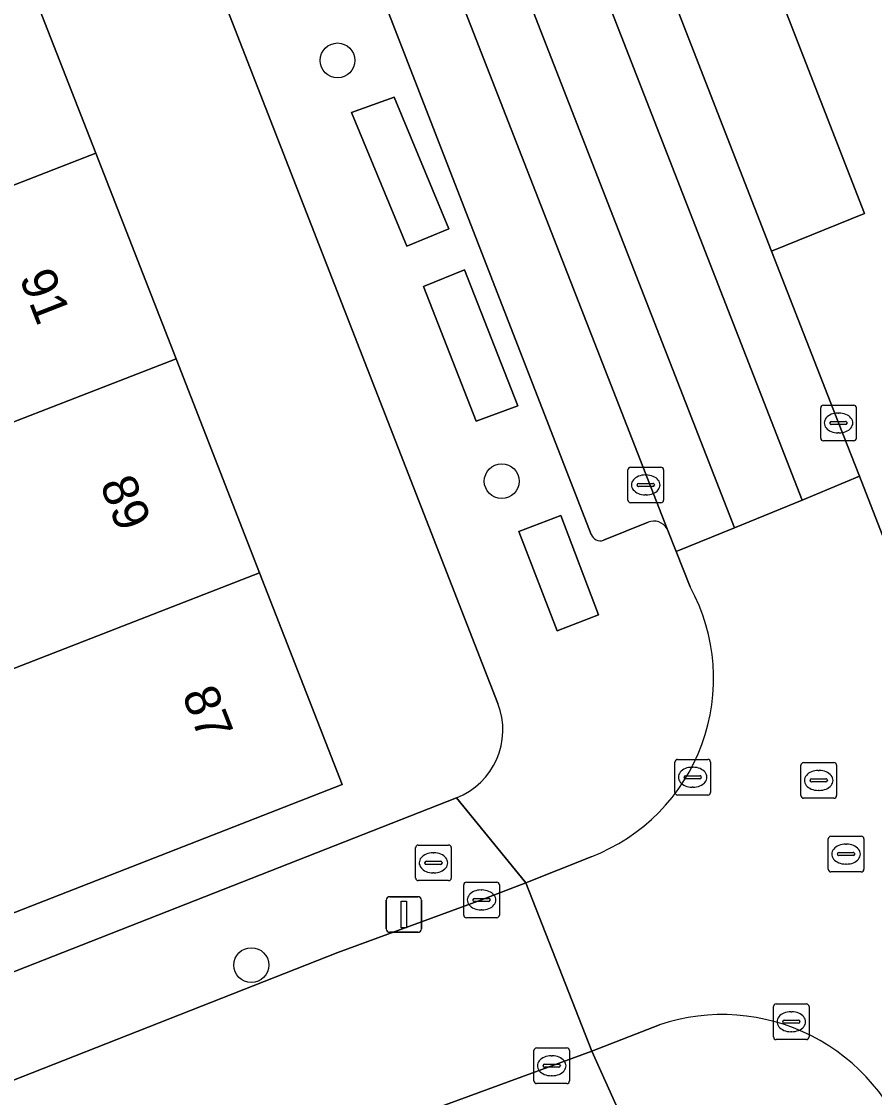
# Model space of a CAD drawing. Extents: x 159680 to 160786, y 387323 to 388340.
# Drawn here: x 160127.91 to 160151.87, y 387907.82 to 387938.03 of the extents above; entities that cross this region are included whole.
import ezdxf

# ---------------------------------------------------------------- set-up
doc = ezdxf.new("R2010")
doc.units = 0
for name, color, linetype in [('IMGEO_Boom', 7, 'Continuous'), ('IMGEO_Brandkraan', 7, 'Continuous'), ('IMGEO_Erf', 7, 'Continuous'), ('IMGEO_Groenvoorziening', 7, 'Continuous'), ('IMGEO_Kolk', 7, 'Continuous'), ('IMGEO_Lichtmast', 7, 'Continuous'), ('IMGEO_Pand', 7, 'Continuous'), ('IMGEO_Pand_nummerreeks', 7, 'Continuous'), ('IMGEO_Parkeervlak_open', 7, 'Continuous'), ('IMGEO_Rijbaan_lokaal_gesloten', 7, 'Continuous'), ('IMGEO_Rijbaan_lokaal_open', 7, 'Continuous'), ('IMGEO_Rioolput', 7, 'Continuous'), ('IMGEO_Voetpad_open', 7, 'Continuous')]:
    doc.layers.add(name, color=color, linetype=linetype)

msp = doc.modelspace()

# ---------------------------------------------------------------- linework, layer by layer
at = {"layer": 'IMGEO_Boom'}
for centre in [(160136.79, 387936.94), (160141.402, 387925.126), (160134.368, 387911.539)]:
    msp.add_circle(centre, 0.489, dxfattribs=at)
at = {"layer": 'IMGEO_Brandkraan'}
for p, q in [((160138.985, 387913.984), (160138.985, 387914.836)), ((160139.06, 387914.91), (160139.912, 387914.91)), ((160139.986, 387914.836), (160139.986, 387913.984)), ((160139.473, 387914.69), (160139.498, 387914.69)), ((160139.244, 387914.404), (160139.244, 387914.416)), ((160139.682, 387914.367), (160139.284, 387914.367)), ((160139.287, 387914.453), (160139.685, 387914.453)), ((160139.728, 387914.416), (160139.728, 387914.404)), ((160139.912, 387913.91), (160139.06, 387913.91)), ((160139.496, 387914.13), (160139.471, 387914.13))]:
    msp.add_line(p, q, dxfattribs=at)
for points in [[(160138.985, 387913.984), (160138.985, 387914.836)], [(160139.06, 387914.91), (160139.912, 387914.91)], [(160139.986, 387914.836), (160139.986, 387913.984)], [(160139.912, 387913.91), (160139.06, 387913.91)]]:
    msp.add_lwpolyline(points, dxfattribs=at)
for centre, radius, start, end in [((160139.062, 387914.834), 0.0765, 91.552, 178.448), ((160139.062, 387914.834), 0.0765, 91.552, 178.448), ((160139.91, 387914.834), 0.0765, 1.552, 88.448), ((160139.91, 387914.834), 0.0765, 1.552, 88.448), ((160139.284, 387914.413), 0.0403, 85.8775, 175.7526), ((160139.281, 387914.403), 0.0366, 178.938, 274.7102), ((160139.685, 387914.41), 0.043, 264.8664, 352.4533), ((160139.689, 387914.415), 0.0386, 1.7309, 96.639), ((160139.062, 387913.986), 0.0765, 181.552, 268.448), ((160139.062, 387913.986), 0.0765, 181.552, 268.448), ((160139.91, 387913.986), 0.0765, 271.552, 358.448), ((160139.91, 387913.986), 0.0765, 271.552, 358.448)]:
    msp.add_arc(centre, radius, start, end, dxfattribs=at)
for centre, major_axis, ratio, start_param, end_param in [((160139.472, 387914.41), (-0.387, 0.002), 0.722429, 4.712389, 7.853982), ((160139.497, 387914.41), (-0.39, 0.002), 0.717154, 1.570796, 4.712389)]:
    msp.add_ellipse(centre, major_axis=major_axis, ratio=ratio, start_param=start_param, end_param=end_param, dxfattribs=at)
at = {"layer": 'IMGEO_Erf'}
for points in [[(160117.173, 387970.931), (160116.204, 387970.698), (160110.655, 387969.121), (160096.541, 387964.792), (160097.787, 387961.694), (160101.244, 387963.071), (160103.173, 387958.229), (160099.716, 387956.852), (160101.306, 387952.888), (160103.114, 387948.275), (160105.857, 387949.308), (160107.114, 387945.971), (160108.578, 387942.084), (160105.834, 387941.051), (160115.683, 387915.296), (160115.897, 387915.38), (160116.002, 387915.162), (160118.459, 387916.115), (160119.792, 387912.679), (160117.335, 387911.726), (160118.086, 387909.722), (160118.757, 387907.847), (160120.676, 387908.594), (160140.13, 387916.234)], [(160141.297, 387918.886), (160132.396, 387941.704)]]:
    msp.add_lwpolyline(points, dxfattribs=at)
msp.add_lwpolyline([(160117.557, 387942.943), (160115.165, 387949.099), (160112.885, 387954.968), (160110.623, 387960.789), (160118.478, 387963.856), (160120.754, 387958.026), (160123.043, 387952.16), (160125.445, 387946.008), (160127.727, 387940.161), (160130.001, 387934.334), (160132.253, 387928.565), (160134.6, 387922.552), (160136.92, 387916.607), (160128.993, 387913.512), (160125.678, 387912.224), (160123.361, 387918.186), (160126.676, 387919.474), (160124.339, 387925.49), (160122.096, 387931.263), (160119.83, 387937.093)], close=True, dxfattribs=at)
msp.add_arc((160139.382, 387918.146), 2.053, 291.3752, 21.1214, dxfattribs=at)
at = {"layer": 'IMGEO_Groenvoorziening'}
msp.add_lwpolyline([(160146.101, 387981.164), (160142.324, 387979.675), (160138.864, 387978.366), (160131.76, 387975.659), (160133.244, 387971.861), (160134.554, 387968.586), (160135.868, 387965.217), (160137.991, 387959.814), (160140.621, 387960.823), (160151.591, 387932.646), (160148.978, 387931.586), (160150.863, 387926.76), (160151.456, 387925.265), (160152.156, 387923.465), (160154.538, 387924.338), (160161.401, 387927.165), (160164.49, 387928.393)], dxfattribs=at)
for points in [[(160138.74, 387931.727), (160139.916, 387932.215), (160138.385, 387935.91), (160137.185, 387935.478)], [(160140.685, 387926.81), (160141.852, 387927.243), (160140.359, 387931.058), (160139.202, 387930.595)], [(160142.963, 387920.925), (160144.125, 387921.377), (160143.065, 387924.166), (160141.879, 387923.716)]]:
    msp.add_lwpolyline(points, close=True, dxfattribs=at)
at = {"layer": 'IMGEO_Kolk'}
for p, q in [((160150.362, 387926.334), (160150.362, 387927.186)), ((160150.437, 387927.26), (160151.289, 387927.26)), ((160151.363, 387927.186), (160151.363, 387926.334)), ((160150.85, 387927.04), (160150.875, 387927.04)), ((160150.621, 387926.754), (160150.621, 387926.766)), ((160151.059, 387926.717), (160150.661, 387926.717)), ((160150.664, 387926.803), (160151.062, 387926.803)), ((160151.105, 387926.766), (160151.105, 387926.754)), ((160151.289, 387926.26), (160150.437, 387926.26)), ((160150.873, 387926.48), (160150.848, 387926.48)), ((160144.948, 387924.594), (160144.948, 387925.446)), ((160145.023, 387925.52), (160145.875, 387925.52)), ((160145.949, 387925.446), (160145.949, 387924.594)), ((160145.25, 387925.063), (160145.648, 387925.063)), ((160145.436, 387925.3), (160145.461, 387925.3)), ((160145.207, 387925.014), (160145.207, 387925.026)), ((160145.645, 387924.977), (160145.247, 387924.977)), ((160145.691, 387925.026), (160145.691, 387925.014)), ((160145.875, 387924.52), (160145.023, 387924.52)), ((160145.459, 387924.74), (160145.434, 387924.74)), ((160146.266, 387916.388), (160146.266, 387917.24)), ((160146.341, 387917.314), (160147.193, 387917.314)), ((160147.267, 387917.24), (160147.267, 387916.388)), ((160146.754, 387917.094), (160146.779, 387917.094)), ((160146.525, 387916.808), (160146.525, 387916.82)), ((160146.963, 387916.771), (160146.565, 387916.771)), ((160146.568, 387916.857), (160146.966, 387916.857)), ((160147.009, 387916.82), (160147.009, 387916.808)), ((160147.193, 387916.314), (160146.341, 387916.314)), ((160146.777, 387916.534), (160146.752, 387916.534)), ((160140.41, 387913.868), (160141.262, 387913.868)), ((160140.335, 387912.942), (160140.335, 387913.794)), ((160140.823, 387913.648), (160140.848, 387913.648)), ((160141.336, 387913.794), (160141.336, 387912.942)), ((160140.594, 387913.362), (160140.594, 387913.374)), ((160141.032, 387913.325), (160140.634, 387913.325)), ((160140.637, 387913.411), (160141.035, 387913.411)), ((160141.078, 387913.374), (160141.078, 387913.362)), ((160140.846, 387913.088), (160140.821, 387913.088)), ((160141.262, 387912.868), (160140.41, 387912.868)), ((160149.036, 387909.522), (160149.036, 387910.374)), ((160149.111, 387910.448), (160149.963, 387910.448)), ((160150.037, 387910.374), (160150.037, 387909.522)), ((160149.295, 387909.942), (160149.295, 387909.954)), ((160149.338, 387909.991), (160149.736, 387909.991)), ((160149.524, 387910.228), (160149.549, 387910.228)), ((160149.779, 387909.954), (160149.779, 387909.942)), ((160149.733, 387909.905), (160149.335, 387909.905)), ((160149.547, 387909.668), (160149.522, 387909.668)), ((160149.963, 387909.448), (160149.111, 387909.448)), ((160142.306, 387908.286), (160142.306, 387909.138)), ((160142.381, 387909.212), (160143.233, 387909.212)), ((160143.307, 387909.138), (160143.307, 387908.286)), ((160142.608, 387908.755), (160143.006, 387908.755)), ((160142.794, 387908.992), (160142.819, 387908.992)), ((160142.565, 387908.706), (160142.565, 387908.718)), ((160143.003, 387908.669), (160142.605, 387908.669)), ((160142.817, 387908.432), (160142.792, 387908.432)), ((160143.049, 387908.718), (160143.049, 387908.706)), ((160143.233, 387908.212), (160142.381, 387908.212))]:
    msp.add_line(p, q, dxfattribs=at)
for points in [[(160150.362, 387926.334), (160150.362, 387927.186)], [(160150.437, 387927.26), (160151.289, 387927.26)], [(160151.363, 387927.186), (160151.363, 387926.334)], [(160151.289, 387926.26), (160150.437, 387926.26)], [(160144.948, 387924.594), (160144.948, 387925.446)], [(160145.023, 387925.52), (160145.875, 387925.52)], [(160145.949, 387925.446), (160145.949, 387924.594)], [(160145.875, 387924.52), (160145.023, 387924.52)], [(160146.266, 387916.388), (160146.266, 387917.24)], [(160146.341, 387917.314), (160147.193, 387917.314)], [(160147.267, 387917.24), (160147.267, 387916.388)], [(160147.193, 387916.314), (160146.341, 387916.314)], [(160140.41, 387913.868), (160141.262, 387913.868)], [(160140.335, 387912.942), (160140.335, 387913.794)], [(160141.336, 387913.794), (160141.336, 387912.942)], [(160141.262, 387912.868), (160140.41, 387912.868)], [(160149.036, 387909.522), (160149.036, 387910.374)], [(160149.111, 387910.448), (160149.963, 387910.448)], [(160150.037, 387910.374), (160150.037, 387909.522)], [(160149.963, 387909.448), (160149.111, 387909.448)], [(160142.306, 387908.286), (160142.306, 387909.138)], [(160142.381, 387909.212), (160143.233, 387909.212)], [(160143.307, 387909.138), (160143.307, 387908.286)], [(160143.233, 387908.212), (160142.381, 387908.212)]]:
    msp.add_lwpolyline(points, dxfattribs=at)
for centre, radius, start, end in [((160150.439, 387927.184), 0.0765, 91.552, 178.448), ((160150.439, 387927.184), 0.0765, 91.552, 178.448), ((160151.287, 387927.184), 0.0765, 1.552, 88.448), ((160151.287, 387927.184), 0.0765, 1.552, 88.448), ((160150.661, 387926.763), 0.0403, 85.8775, 175.7526), ((160150.658, 387926.753), 0.0366, 178.938, 274.7102), ((160151.062, 387926.76), 0.043, 264.8664, 352.4533), ((160151.066, 387926.765), 0.0386, 1.7309, 96.639), ((160150.439, 387926.336), 0.0765, 181.552, 268.448), ((160150.439, 387926.336), 0.0765, 181.552, 268.448), ((160151.287, 387926.336), 0.0765, 271.552, 358.448), ((160151.287, 387926.336), 0.0765, 271.552, 358.448), ((160145.025, 387925.444), 0.0765, 91.552, 178.448), ((160145.025, 387925.444), 0.0765, 91.552, 178.448), ((160145.873, 387925.444), 0.0765, 1.552, 88.448), ((160145.873, 387925.444), 0.0765, 1.552, 88.448), ((160145.247, 387925.023), 0.0403, 85.8775, 175.7526), ((160145.652, 387925.025), 0.0386, 1.7309, 96.639), ((160145.244, 387925.013), 0.0366, 178.938, 274.7102), ((160145.648, 387925.02), 0.043, 264.8664, 352.4533), ((160145.025, 387924.596), 0.0765, 181.552, 268.448), ((160145.025, 387924.596), 0.0765, 181.552, 268.448), ((160145.873, 387924.596), 0.0765, 271.552, 358.448), ((160145.873, 387924.596), 0.0765, 271.552, 358.448), ((160146.343, 387917.238), 0.0765, 91.552, 178.448), ((160146.343, 387917.238), 0.0765, 91.552, 178.448), ((160147.191, 387917.238), 0.0765, 1.552, 88.448), ((160147.191, 387917.238), 0.0765, 1.552, 88.448), ((160146.565, 387916.817), 0.0403, 85.8775, 175.7526), ((160146.562, 387916.807), 0.0366, 178.938, 274.7102), ((160146.966, 387916.814), 0.043, 264.8664, 352.4533), ((160146.97, 387916.819), 0.0386, 1.7309, 96.639), ((160146.343, 387916.39), 0.0765, 181.552, 268.448), ((160146.343, 387916.39), 0.0765, 181.552, 268.448), ((160147.191, 387916.39), 0.0765, 271.552, 358.448), ((160147.191, 387916.39), 0.0765, 271.552, 358.448), ((160140.412, 387913.792), 0.0765, 91.552, 178.448), ((160140.412, 387913.792), 0.0765, 91.552, 178.448), ((160141.26, 387913.792), 0.0765, 1.552, 88.448), ((160141.26, 387913.792), 0.0765, 1.552, 88.448), ((160140.634, 387913.371), 0.0403, 85.8775, 175.7526), ((160140.631, 387913.361), 0.0366, 178.938, 274.7102), ((160141.035, 387913.368), 0.043, 264.8664, 352.4533), ((160141.039, 387913.373), 0.0386, 1.7309, 96.639), ((160140.412, 387912.944), 0.0765, 181.552, 268.448), ((160140.412, 387912.944), 0.0765, 181.552, 268.448), ((160141.26, 387912.944), 0.0765, 271.552, 358.448), ((160141.26, 387912.944), 0.0765, 271.552, 358.448), ((160149.113, 387910.372), 0.0765, 91.552, 178.448), ((160149.113, 387910.372), 0.0765, 91.552, 178.448), ((160149.961, 387910.372), 0.0765, 1.552, 88.448), ((160149.961, 387910.372), 0.0765, 1.552, 88.448), ((160149.335, 387909.951), 0.0403, 85.8775, 175.7526), ((160149.332, 387909.941), 0.0366, 178.938, 274.7102), ((160149.736, 387909.948), 0.043, 264.8664, 352.4533), ((160149.74, 387909.953), 0.0386, 1.7309, 96.639), ((160149.113, 387909.524), 0.0765, 181.552, 268.448), ((160149.113, 387909.524), 0.0765, 181.552, 268.448), ((160149.961, 387909.524), 0.0765, 271.552, 358.448), ((160149.961, 387909.524), 0.0765, 271.552, 358.448), ((160142.383, 387909.136), 0.0765, 91.552, 178.448), ((160142.383, 387909.136), 0.0765, 91.552, 178.448), ((160143.231, 387909.136), 0.0765, 1.552, 88.448), ((160143.231, 387909.136), 0.0765, 1.552, 88.448), ((160142.605, 387908.715), 0.0403, 85.8775, 175.7526), ((160143.01, 387908.717), 0.0386, 1.7309, 96.639), ((160142.602, 387908.705), 0.0366, 178.938, 274.7102), ((160143.006, 387908.712), 0.043, 264.8664, 352.4533), ((160142.383, 387908.288), 0.0765, 181.552, 268.448), ((160142.383, 387908.288), 0.0765, 181.552, 268.448), ((160143.231, 387908.288), 0.0765, 271.552, 358.448), ((160143.231, 387908.288), 0.0765, 271.552, 358.448)]:
    msp.add_arc(centre, radius, start, end, dxfattribs=at)
for centre, major_axis, ratio, start_param, end_param in [((160150.849, 387926.76), (-0.387, 0.002), 0.722429, 4.712389, 7.853982), ((160150.874, 387926.76), (-0.39, 0.002), 0.717154, 1.570796, 4.712389), ((160145.435, 387925.02), (-0.387, 0.002), 0.722429, 4.712389, 7.853982), ((160145.46, 387925.02), (-0.39, 0.002), 0.717154, 1.570796, 4.712389), ((160146.753, 387916.814), (-0.387, 0.002), 0.722429, 4.712389, 7.853982), ((160146.778, 387916.814), (-0.39, 0.002), 0.717154, 1.570796, 4.712389), ((160140.822, 387913.368), (-0.387, 0.002), 0.722429, 4.712389, 7.853982), ((160140.847, 387913.368), (-0.39, 0.002), 0.717154, 1.570796, 4.712389), ((160149.523, 387909.948), (-0.387, 0.002), 0.722429, 4.712389, 7.853982), ((160149.548, 387909.948), (-0.39, 0.002), 0.717154, 1.570796, 4.712389), ((160142.793, 387908.712), (-0.387, 0.002), 0.722429, 4.712389, 7.853982), ((160142.818, 387908.712), (-0.39, 0.002), 0.717154, 1.570796, 4.712389)]:
    msp.add_ellipse(centre, major_axis=major_axis, ratio=ratio, start_param=start_param, end_param=end_param, dxfattribs=at)
at = {"layer": 'IMGEO_Lichtmast'}
for p, q in [((160138.157, 387912.56), (160138.157, 387913.36)), ((160138.157, 387913.36), (160138.157, 387912.56)), ((160138.257, 387913.46), (160139.047, 387913.46)), ((160139.047, 387913.46), (160138.257, 387913.46)), ((160139.147, 387913.36), (160139.147, 387912.56)), ((160139.147, 387912.56), (160139.147, 387913.36)), ((160139.047, 387912.46), (160138.257, 387912.46)), ((160138.257, 387912.46), (160139.047, 387912.46))]:
    msp.add_line(p, q, dxfattribs=at)
msp.add_lwpolyline([(160138.577, 387913.335), (160138.727, 387913.335), (160138.727, 387912.585), (160138.577, 387912.585), (160138.577, 387913.335)], dxfattribs=at)
for centre, start, end in [((160138.257, 387913.36), 90, 180), ((160138.257, 387913.36), 90, 180), ((160139.047, 387913.36), 0, 90), ((160139.047, 387913.36), 360, 90), ((160138.257, 387912.56), 180, 270), ((160138.257, 387912.56), 180, 270), ((160139.047, 387912.56), 270, 0), ((160139.047, 387912.56), 270, 0)]:
    msp.add_arc(centre, 0.1, start, end, dxfattribs=at)
at = {"layer": 'IMGEO_Pand'}
for points in [[(160130.001, 387934.334), (160127.727, 387940.161), (160119.83, 387937.093), (160122.096, 387931.263)], [(160122.096, 387931.263), (160124.339, 387925.49), (160132.253, 387928.565), (160130.001, 387934.334)], [(160134.6, 387922.552), (160132.253, 387928.565), (160124.339, 387925.49), (160126.676, 387919.474)], [(160134.6, 387922.552), (160126.676, 387919.474), (160123.361, 387918.186), (160125.678, 387912.224), (160128.993, 387913.512), (160136.92, 387916.607)]]:
    msp.add_lwpolyline(points, close=True, dxfattribs=at)
at = {"layer": 'IMGEO_Parkeervlak_open'}
for points in [[(160146.047, 387923.792), (160130.492, 387963.653)], [(160128.848, 387962.268), (160129.136, 387961.665), (160143.916, 387923.629)], [(160144.26, 387923.466), (160145.519, 387923.974)]]:
    msp.add_lwpolyline(points, dxfattribs=at)
msp.add_lwpolyline([(160137.991, 387959.814), (160143.514, 387945.629), (160148.978, 387931.586), (160151.591, 387932.646), (160140.621, 387960.823)], close=True, dxfattribs=at)
for centre, radius, start, end in [((160145.678, 387923.579), 0.426, 30.0107, 111.9515), ((160144.177, 387923.736), 0.282, 202.1965, 287.0968)]:
    msp.add_arc(centre, radius, start, end, dxfattribs=at)
at = {"layer": 'IMGEO_Rijbaan_lokaal_gesloten'}
for points in [[(160137.991, 387959.814), (160135.868, 387965.217), (160134.554, 387968.586), (160132.955, 387967.915), (160149.838, 387924.597), (160151.456, 387925.265), (160150.863, 387926.76), (160148.978, 387931.586), (160143.514, 387945.629)], [(160131.042, 387967.15), (160129.403, 387966.471), (160130.344, 387964.037), (160130.492, 387963.653), (160146.047, 387923.792), (160146.305, 387923.152), (160147.944, 387923.815)]]:
    msp.add_lwpolyline(points, close=True, dxfattribs=at)
at = {"layer": 'IMGEO_Rijbaan_lokaal_open'}
msp.add_lwpolyline([(160132.955, 387967.915), (160131.042, 387967.15), (160147.944, 387923.815), (160149.838, 387924.597)], close=True, dxfattribs=at)
for points in [[(160153.052, 387921.218), (160152.156, 387923.465), (160151.456, 387925.265), (160149.838, 387924.597), (160147.944, 387923.815), (160146.305, 387923.152), (160146.7, 387922.155)], [(160143.916, 387914.582), (160142.084, 387913.853), (160143.935, 387909.124), (160145.839, 387909.866)], [(160138.953, 387907.297), (160142.807, 387908.712), (160143.935, 387909.124), (160142.084, 387913.853), (160140.836, 387913.368), (160136.795, 387911.888), (160118.168, 387904.562)]]:
    msp.add_lwpolyline(points, dxfattribs=at)
for centre, radius, start, end in [((160141.997, 387919.586), 5.359, 290.9811, 28.6498), ((160147.594, 387904.599), 5.552, 17.7433, 108.4323)]:
    msp.add_arc(centre, radius, start, end, dxfattribs=at)
at = {"layer": 'IMGEO_Rioolput'}
for p, q in [((160149.882, 387917.224), (160150.734, 387917.224)), ((160149.807, 387916.298), (160149.807, 387917.15)), ((160150.295, 387917.004), (160150.32, 387917.004)), ((160150.808, 387917.15), (160150.808, 387916.298)), ((160150.066, 387916.718), (160150.066, 387916.73)), ((160150.504, 387916.681), (160150.106, 387916.681)), ((160150.109, 387916.767), (160150.507, 387916.767)), ((160150.55, 387916.73), (160150.55, 387916.718)), ((160150.318, 387916.444), (160150.293, 387916.444)), ((160150.734, 387916.224), (160149.882, 387916.224)), ((160150.575, 387914.229), (160150.575, 387915.081)), ((160150.65, 387915.155), (160151.502, 387915.155)), ((160151.576, 387915.081), (160151.576, 387914.229)), ((160151.063, 387914.935), (160151.088, 387914.935)), ((160150.834, 387914.649), (160150.834, 387914.661)), ((160151.272, 387914.612), (160150.874, 387914.612)), ((160150.877, 387914.698), (160151.275, 387914.698)), ((160151.318, 387914.661), (160151.318, 387914.649)), ((160151.086, 387914.375), (160151.061, 387914.375)), ((160151.502, 387914.155), (160150.65, 387914.155))]:
    msp.add_line(p, q, dxfattribs=at)
for points in [[(160149.882, 387917.224), (160150.734, 387917.224)], [(160149.807, 387916.298), (160149.807, 387917.15)], [(160150.808, 387917.15), (160150.808, 387916.298)], [(160150.734, 387916.224), (160149.882, 387916.224)], [(160150.575, 387914.229), (160150.575, 387915.081)], [(160150.65, 387915.155), (160151.502, 387915.155)], [(160151.576, 387915.081), (160151.576, 387914.229)], [(160151.502, 387914.155), (160150.65, 387914.155)]]:
    msp.add_lwpolyline(points, dxfattribs=at)
for centre, radius, start, end in [((160149.884, 387917.148), 0.0765, 91.552, 178.448), ((160149.884, 387917.148), 0.0765, 91.552, 178.448), ((160150.732, 387917.148), 0.0765, 1.552, 88.448), ((160150.732, 387917.148), 0.0765, 1.552, 88.448), ((160150.106, 387916.727), 0.0403, 85.8775, 175.7526), ((160150.103, 387916.717), 0.0366, 178.938, 274.7102), ((160150.507, 387916.724), 0.043, 264.8664, 352.4533), ((160150.511, 387916.729), 0.0386, 1.7309, 96.639), ((160149.884, 387916.3), 0.0765, 181.552, 268.448), ((160149.884, 387916.3), 0.0765, 181.552, 268.448), ((160150.732, 387916.3), 0.0765, 271.552, 358.448), ((160150.732, 387916.3), 0.0765, 271.552, 358.448), ((160150.652, 387915.079), 0.0765, 91.552, 178.448), ((160150.652, 387915.079), 0.0765, 91.552, 178.448), ((160151.5, 387915.079), 0.0765, 1.552, 88.448), ((160151.5, 387915.079), 0.0765, 1.552, 88.448), ((160150.874, 387914.658), 0.0403, 85.8775, 175.7526), ((160150.871, 387914.648), 0.0366, 178.938, 274.7102), ((160151.275, 387914.655), 0.043, 264.8664, 352.4533), ((160151.279, 387914.66), 0.0386, 1.7309, 96.639), ((160150.652, 387914.231), 0.0765, 181.552, 268.448), ((160150.652, 387914.231), 0.0765, 181.552, 268.448), ((160151.5, 387914.231), 0.0765, 271.552, 358.448), ((160151.5, 387914.231), 0.0765, 271.552, 358.448)]:
    msp.add_arc(centre, radius, start, end, dxfattribs=at)
for centre, major_axis, ratio, start_param, end_param in [((160150.294, 387916.724), (-0.387, 0.002), 0.722429, 4.712389, 7.853982), ((160150.319, 387916.724), (-0.39, 0.002), 0.717154, 1.570796, 4.712389), ((160151.062, 387914.655), (-0.387, 0.002), 0.722429, 4.712389, 7.853982), ((160151.087, 387914.655), (-0.39, 0.002), 0.717154, 1.570796, 4.712389)]:
    msp.add_ellipse(centre, major_axis=major_axis, ratio=ratio, start_param=start_param, end_param=end_param, dxfattribs=at)
at = {"layer": 'IMGEO_Voetpad_open'}
for points in [[(160120.305, 387969.359), (160127.759, 387952.904), (160132.396, 387941.704), (160141.297, 387918.886)], [(160143.916, 387923.629), (160129.136, 387961.665)], [(160145.519, 387923.974), (160144.26, 387923.466)], [(160146.7, 387922.155), (160146.305, 387923.152), (160146.047, 387923.792)], [(160114.072, 387911.049), (160114.271, 387910.688), (160114.869, 387909.226), (160115.857, 387906.811), (160118.168, 387904.562), (160136.795, 387911.888), (160140.836, 387913.368), (160142.084, 387913.853), (160140.13, 387916.234), (160120.676, 387908.594), (160118.757, 387907.847), (160118.086, 387909.722), (160117.335, 387911.726), (160116.002, 387915.162), (160115.897, 387915.38), (160115.683, 387915.296), (160114.506, 387914.836), (160061.446, 387894.107), (160060.118, 387893.588), (160001.03, 387870.503), (160000, 387870.101), (159999.652, 387869.965), (160000, 387869.051), (160001.74, 387864.48)], [(160140.13, 387916.234), (160142.084, 387913.853), (160143.916, 387914.582)], [(160145.839, 387909.866), (160143.935, 387909.124), (160145.167, 387906.383)]]:
    msp.add_lwpolyline(points, dxfattribs=at)
for points in [[(160138.74, 387931.727), (160137.185, 387935.478), (160138.385, 387935.91), (160139.916, 387932.215)], [(160140.359, 387931.058), (160141.852, 387927.243), (160140.685, 387926.81), (160139.202, 387930.595)], [(160143.065, 387924.166), (160144.125, 387921.377), (160142.963, 387920.925), (160141.879, 387923.716)], [(160139.873, 387904.403), (160145.167, 387906.383), (160143.935, 387909.124), (160142.807, 387908.712), (160138.953, 387907.297), (160139.187, 387906.687), (160119.143, 387898.892), (160118.964, 387899.358), (160116.683, 387898.471), (160116.862, 387898.005), (160102.246, 387892.32), (160102.067, 387892.786), (160095.351, 387890.173), (160095.53, 387889.707), (160090.509, 387887.754), (160091.41, 387885.467), (160096.393, 387887.443)]]:
    msp.add_lwpolyline(points, close=True, dxfattribs=at)
for centre, radius, start, end in [((160145.678, 387923.579), 0.426, 30.0107, 111.9515), ((160144.177, 387923.736), 0.282, 202.1965, 287.0968), ((160141.997, 387919.586), 5.359, 290.9811, 28.6498), ((160139.382, 387918.146), 2.053, 291.3752, 21.1214), ((160147.594, 387904.599), 5.552, 17.7433, 108.4323)]:
    msp.add_arc(centre, radius, start, end, dxfattribs=at)

# ---------------------------------------------------------------- texts
at = {"layer": 'IMGEO_Pand_nummerreeks'}
for s, rotation, p in [('91', 291.3215, (160127.842, 387930.844)), ('89', 291.3215, (160130.107, 387925.043)), ('87', 291.3195, (160132.411, 387919.138))]:
    msp.add_text(s, height=1, rotation=rotation, dxfattribs=at).set_placement(p)

doc.saveas('drawing.dxf')
